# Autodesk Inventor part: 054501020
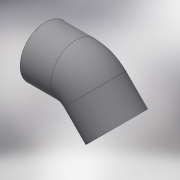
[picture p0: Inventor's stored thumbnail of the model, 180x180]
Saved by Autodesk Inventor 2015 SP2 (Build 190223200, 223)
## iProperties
Created: 2017-10
Part Number: 054501020
Material: Generic
Description: PLASSON THREADED 45° ELBOW HF 2"
Document SubType Name: Modeling
Designer: KIM
Mass: 156.777 g
Surface Area: 369.731 cm^2
Volume: 156.777 cm^3
Density: 1 g/cm^3
Appearance: Default
Author: KIM
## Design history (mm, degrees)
derived "054501.ipt"
feature "Solid1::054501.ipt"
tag "TaggingFeature1"
body "Solid1"
other parameters: "d7" = 0.56656, "d9" = 74, "d13" = 135 deg, "d18" = 15, "d19" = 45 deg, "d20" = 56.656, "d21" = 26, "d22" = 0, "d28" = 41, "d29" = 56.656, "d30" = 26, "d31" = 0, "d32" = 50.9904, "d33" = 45 deg, "E_" = 74, "lt_" = 26, "Z_" = 15, "G_" = 56.656
